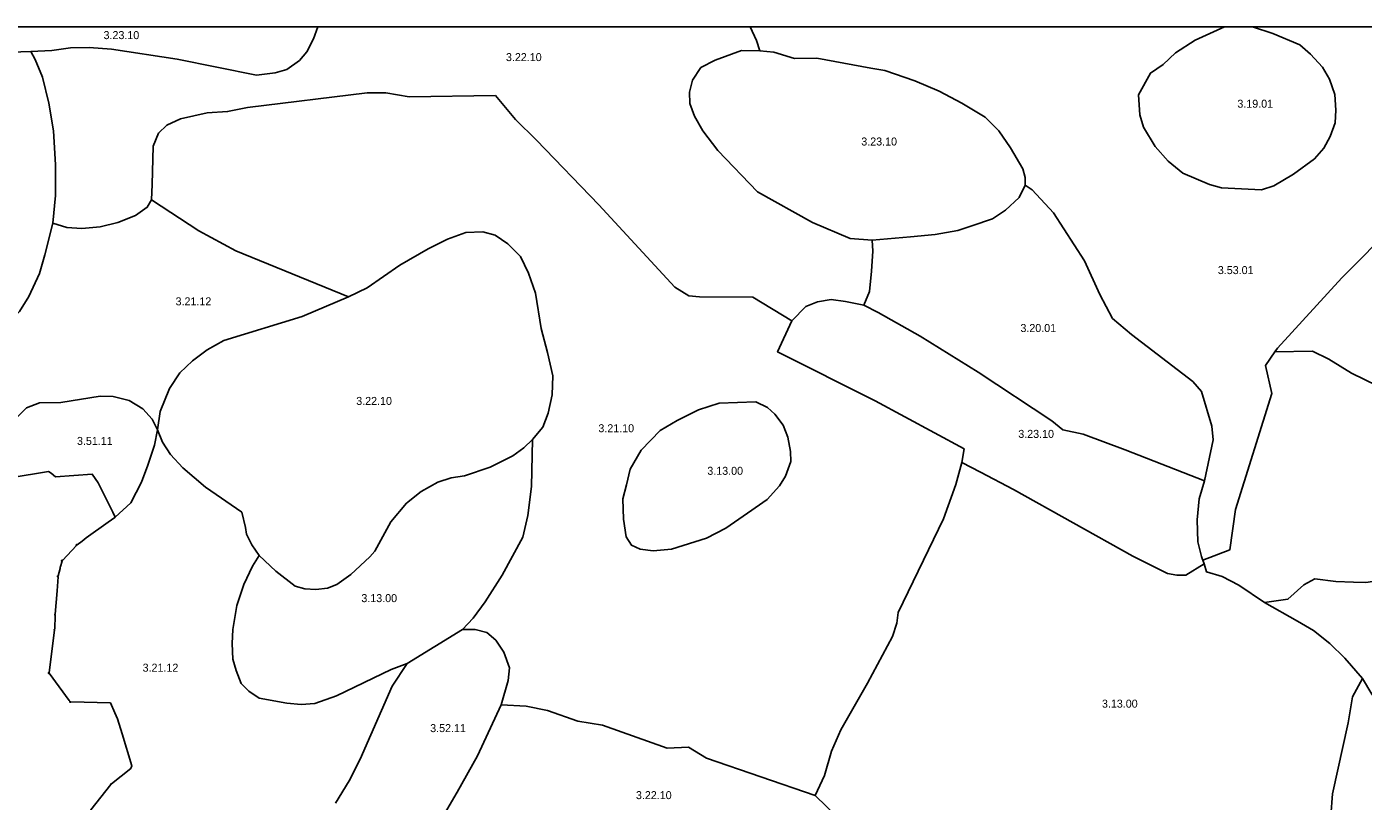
# Model space of a CAD drawing. Extents: x -662500 to -653478, y -1056827 to -1049993.
# Drawn here: x -661381 to -660129, y -1050726 to -1050000 of the extents above; entities that cross this region are included whole.
import ezdxf

# ---------------------------------------------------------------- set-up
doc = ezdxf.new("R2010")
doc.units = 0
doc.layers.add('Vrstva 24', color=7, linetype='Continuous')

msp = doc.modelspace()

# ---------------------------------------------------------------- linework, layer by layer
at = {"layer": 'Vrstva 24'}
for points in [[(-661523.5, -1050000), (-661108.3, -1050000)], [(-661377.4, -1050023.3), (-661357.8, -1050022.2), (-661340.2, -1050019.7), (-661322.6, -1050019.4), (-661301.7, -1050021.1), (-661240.1, -1050030.4), (-661165.8, -1050045.3), (-661148.3, -1050043.1), (-661137.3, -1050040.1), (-661125.7, -1050031.8), (-661118.6, -1050023.6), (-661112.5, -1050011.2), (-661108.3, -1050000)], [(-661108.3, -1050000), (-660703.4, -1050000)], [(-660703.4, -1050000), (-660258.7, -1050000)], [(-660694.1, -1050022.7), (-660697.3, -1050012.8), (-660703.4, -1050000)], [(-660258.7, -1050000), (-660286.3, -1050012.7), (-660304.7, -1050024.5), (-660316.3, -1050035.5), (-660328.1, -1050043.5), (-660339.4, -1050063.9), (-660338.1, -1050082.6), (-660334.8, -1050094.2), (-660323.7, -1050112.1), (-660311.6, -1050126.1), (-660297.8, -1050137.1), (-660272.8, -1050147.9), (-660261.5, -1050150.9), (-660224.1, -1050152.8), (-660212.5, -1050149.2), (-660194, -1050138.2), (-660174.5, -1050123.9), (-660165.7, -1050113.7), (-660159.6, -1050103), (-660155.2, -1050090), (-660154.4, -1050078.2), (-660155.5, -1050063.6), (-660160.5, -1050049), (-660166.8, -1050038), (-660178.3, -1050025.6), (-660188.3, -1050017.1), (-660213.6, -1050006.3), (-660232.6, -1050000)], [(-660258.7, -1050000), (-660232.6, -1050000)], [(-660232.6, -1050000), (-660083.8, -1050000)], [(-660211.6, -1050304.5), (-660209.1, -1050301.1), (-660148.9, -1050235.3), (-660049.3, -1050135), (-660047.7, -1050118.2), (-660049.1, -1050094), (-660056.1, -1050060.4), (-660067.9, -1050029.3), (-660083.8, -1050000)], [(-661463.8, -1050026.3), (-661450.6, -1050027.4), (-661433.8, -1050025.2), (-661377.4, -1050023.3)], [(-661377.4, -1050023.3), (-661373.2, -1050030.7), (-661366.5, -1050047.2), (-661360.4, -1050071.7), (-661356, -1050097.4), (-661354.1, -1050129.3), (-661354.2, -1050158.2), (-661356.7, -1050184.1)], [(-660694.1, -1050022.7), (-660711.4, -1050022.2), (-660735.9, -1050031.3), (-660749.4, -1050038.2), (-660757.4, -1050050), (-660760.1, -1050061.3), (-660759.9, -1050071.8), (-660755.5, -1050083.9), (-660747.5, -1050097.6), (-660733.4, -1050116.1), (-660696.4, -1050154.6), (-660644.9, -1050183.3), (-660609.4, -1050198.4), (-660588.9, -1050200.1)], [(-660445.7, -1050148.6), (-660445.7, -1050141.4), (-660447.8, -1050133.2), (-660459.3, -1050113.6), (-660470.1, -1050097.6), (-660483, -1050084.7), (-660505, -1050071.5), (-660526, -1050060.5), (-660548.8, -1050050.6), (-660577, -1050040.9), (-660590.2, -1050038.7), (-660640.9, -1050029.6), (-660661.6, -1050029.9), (-660681.1, -1050023.8), (-660694.1, -1050022.7)], [(-660664.2, -1050275.5), (-660700.8, -1050253.5), (-660750.6, -1050253.2), (-660760.8, -1050252.1), (-660774, -1050243.9), (-660845.2, -1050167), (-660903.6, -1050106.4), (-660923.3, -1050086.9), (-660942, -1050064.3), (-661022.7, -1050065.7), (-661044.7, -1050061.8), (-661062.3, -1050061.8), (-661174.3, -1050075.6), (-661193, -1050079.5), (-661212, -1050080.6), (-661237.2, -1050086.4), (-661249.8, -1050092.1), (-661257.8, -1050099.6), (-661262.8, -1050111.9), (-661263.6, -1050148), (-661264.2, -1050162.1)], [(-661356.7, -1050184.1), (-661364.2, -1050213.8), (-661369.1, -1050231.4), (-661379.3, -1050252.9), (-661388.1, -1050267), (-661399.4, -1050279.1), (-661411, -1050288.2), (-661419.5, -1050291.5), (-661429.7, -1050291.5), (-661439.6, -1050289.5), (-661453.1, -1050281), (-661463.8, -1050267.8), (-661469.1, -1050256.8), (-661473.6, -1050232.3), (-661477.7, -1050204.7), (-661479.4, -1050161.5), (-661478.8, -1050137), (-661473.6, -1050080.3)], [(-660588.9, -1050200.1), (-660553.1, -1050196.8), (-660529.9, -1050194.8), (-660508.7, -1050191), (-660495.5, -1050186.6), (-660476.2, -1050180), (-660464.1, -1050172), (-660451.2, -1050160.1), (-660445.7, -1050148.6)], [(-660277.5, -1050425.5), (-660269.5, -1050387), (-660270.6, -1050374.3), (-660280.2, -1050341.8), (-660288.5, -1050332.5), (-660346, -1050288.4), (-660363.7, -1050273.3), (-660375.5, -1050251), (-660390, -1050219.3), (-660418.9, -1050174.4), (-660439, -1050152.9), (-660445.7, -1050148.6)], [(-661356.7, -1050184.1), (-661343.6, -1050188.1), (-661329.6, -1050189.2), (-661312.5, -1050187.6), (-661295.7, -1050183.5), (-661279.2, -1050176.9), (-661268.2, -1050169.1), (-661264.2, -1050162.1)], [(-661264.2, -1050162.1), (-661220, -1050191.2), (-661185.3, -1050210), (-661079.8, -1050253.2)], [(-661079.8, -1050253.2), (-661062.2, -1050244.7), (-661031.5, -1050223.5), (-661005.1, -1050208.1), (-660986.9, -1050199), (-660969.8, -1050192.9), (-660953.8, -1050192.1), (-660942.3, -1050195.4), (-660930.4, -1050203.6), (-660918.6, -1050215.2), (-660910.9, -1050230.9), (-660904.3, -1050249.6), (-660899.2, -1050282.7), (-660893.1, -1050305.2), (-660888.2, -1050327), (-660888.7, -1050344.9), (-660892.6, -1050362), (-660897.7, -1050375.2), (-660907.3, -1050386.8)], [(-660596.7, -1050260.9), (-660591.5, -1050248.2), (-660589.6, -1050229.2), (-660588.2, -1050210.2), (-660588.9, -1050200.1)], [(-661079.8, -1050253.2), (-661123, -1050271.4), (-661196.4, -1050294), (-661212.1, -1050302.8), (-661225.9, -1050313), (-661237.7, -1050324.2), (-661247.4, -1050339.1), (-661256.2, -1050360.6), (-661258.5, -1050377.9)], [(-660596.7, -1050260.9), (-660613.8, -1050257.6), (-660627.3, -1050255.7), (-660640.2, -1050257.9), (-660651.2, -1050262.3), (-660664.2, -1050275.5)], [(-660277.5, -1050425.5), (-660352, -1050396.6), (-660391.3, -1050381.8), (-660410.3, -1050377.9), (-660420.7, -1050369.4), (-660489.5, -1050323.6), (-660544, -1050290.1), (-660583.2, -1050267.8), (-660596.7, -1050260.9)], [(-660505, -1050408.5), (-660502.8, -1050395.6), (-660586, -1050350.7), (-660677.5, -1050304.7), (-660664.2, -1050275.5)], [(-660279.1, -1050499.9), (-660253.8, -1050490.3), (-660248.4, -1050452.3), (-660214.5, -1050343.8), (-660220.3, -1050317.6), (-660211.6, -1050304.5)], [(-660211.6, -1050304.5), (-660176.2, -1050303.9), (-660161.1, -1050311.5), (-660139.9, -1050324.5), (-660079.5, -1050353.9), (-660071.9, -1050356.5), (-660062.9, -1050361.1), (-660057, -1050366.9), (-660044.6, -1050380.4)], [(-661258.5, -1050377.9), (-661263.6, -1050367.8), (-661272.4, -1050358.1), (-661285.1, -1050350.1), (-661300.2, -1050346.6), (-661312.3, -1050346.3), (-661349.2, -1050352.1), (-661369.1, -1050352.3), (-661381.5, -1050357), (-661395.8, -1050371.6), (-661404.9, -1050386.2), (-661415.3, -1050423.4), (-661417.3, -1050430.4)], [(-661298.2, -1050459.6), (-661298.2, -1050459.7), (-661283.5, -1050446.3), (-661273.7, -1050426.7), (-661267.6, -1050410.7), (-661261.5, -1050392), (-661258.5, -1050377.9)], [(-661258.5, -1050377.9), (-661253.8, -1050389.2), (-661246.4, -1050400.8), (-661234.8, -1050413.2), (-661213.6, -1050431.6), (-661179.6, -1050455), (-661176.1, -1050469.4), (-661175.2, -1050475.4), (-661170.3, -1050485.6), (-661163.5, -1050495.5)], [(-661163.5, -1050495.5), (-661147.8, -1050510.1), (-661129.7, -1050524.1), (-661120.6, -1050526.6), (-661110.4, -1050527.4), (-661099.4, -1050526.1), (-661090.6, -1050522.8), (-661077.6, -1050513.4), (-661059.7, -1050496.9), (-661054.9, -1050491.4), (-661040, -1050463.9), (-661025.4, -1050446.5), (-661011.7, -1050435.5), (-660996, -1050426.7), (-660983.6, -1050422.8), (-660970.9, -1050420.9), (-660947, -1050412.6), (-660925.8, -1050402.2), (-660915.3, -1050394.7), (-660907.3, -1050386.8)], [(-660972.8, -1050564.9), (-660962.7, -1050554.2), (-660951.6, -1050539), (-660935.7, -1050514), (-660916.3, -1050478.4), (-660911.6, -1050458.1), (-660908.3, -1050430.8), (-660907.3, -1050386.8)], [(-660642.4, -1050720.5), (-660633.7, -1050701.7), (-660627.1, -1050678.9), (-660618.3, -1050658.8), (-660593.3, -1050615), (-660570, -1050571.5), (-660565.9, -1050558.8), (-660564.5, -1050548.8), (-660522, -1050461.1), (-660510.5, -1050429.1), (-660505, -1050408.5)], [(-660277.9, -1050503.2), (-660295.1, -1050513.9), (-660303.4, -1050513.9), (-660312.2, -1050512.3), (-660344.7, -1050496), (-660456.6, -1050433.8), (-660487.4, -1050417.3), (-660505, -1050408.5)], [(-661298.2, -1050459.6), (-661300.5, -1050454.9), (-661311.1, -1050433.8), (-661314.2, -1050427.5), (-661319.8, -1050419.4), (-661354.2, -1050421.7), (-661358.3, -1050418.4), (-661360.9, -1050416.9), (-661396.8, -1050422.6), (-661417.3, -1050430.4)], [(-660277.5, -1050425.5), (-660282.4, -1050442.3), (-660284.4, -1050462.1), (-660283.8, -1050482.8), (-660280.4, -1050496.3), (-660279.7, -1050498.3), (-660279.1, -1050499.9)], [(-661298.2, -1050459.6), (-661298.5, -1050459.8), (-661304.8, -1050464.3), (-661325.6, -1050478.8), (-661329.2, -1050482), (-661334, -1050485.5), (-661334, -1050485.4), (-661334, -1050485.4), (-661334, -1050485.4), (-661334, -1050485.4), (-661334.1, -1050485.4), (-661334.1, -1050485.3), (-661334.1, -1050485.3), (-661334.2, -1050485.3), (-661334.2, -1050485.3), (-661334.2, -1050485.3), (-661334.2, -1050485.3), (-661334.3, -1050485.3), (-661334.3, -1050485.3), (-661334.3, -1050485.3), (-661334.4, -1050485.3), (-661334.4, -1050485.3), (-661334.4, -1050485.3), (-661334.5, -1050485.3), (-661334.5, -1050485.3), (-661334.5, -1050485.3), (-661334.5, -1050485.3), (-661334.6, -1050485.3), (-661334.6, -1050485.3), (-661334.6, -1050485.3), (-661334.7, -1050485.4), (-661334.7, -1050485.4), (-661334.7, -1050485.4), (-661334.7, -1050485.4), (-661334.8, -1050485.5), (-661334.8, -1050485.5), (-661334.8, -1050485.5), (-661334.8, -1050485.6), (-661334.8, -1050485.6), (-661334.8, -1050485.6), (-661334.8, -1050485.6), (-661334.8, -1050485.7), (-661334.9, -1050485.7), (-661334.9, -1050485.7), (-661334.9, -1050485.8), (-661334.9, -1050485.8), (-661334.9, -1050485.8), (-661334.8, -1050485.9), (-661334.8, -1050485.9), (-661334.8, -1050485.9), (-661334.8, -1050485.9), (-661334.8, -1050486), (-661334.8, -1050486), (-661334.8, -1050486), (-661334.8, -1050486.1), (-661334.7, -1050486.1), (-661334.7, -1050486.1), (-661334.7, -1050486.1), (-661347.7, -1050500.1), (-661347.7, -1050500.1), (-661347.7, -1050500.1), (-661347.8, -1050500.1), (-661347.8, -1050500), (-661347.8, -1050500), (-661347.8, -1050500)], [(-661347.8, -1050500), (-661347.9, -1050500), (-661347.9, -1050500), (-661347.9, -1050500), (-661347.9, -1050500), (-661348, -1050500), (-661348, -1050500), (-661348, -1050500), (-661348.1, -1050500), (-661348.1, -1050500), (-661348.1, -1050500), (-661348.2, -1050500), (-661348.2, -1050500), (-661348.2, -1050500), (-661348.2, -1050500), (-661348.3, -1050500.1), (-661348.3, -1050500.1), (-661348.3, -1050500.1), (-661348.4, -1050500.1), (-661348.4, -1050500.1), (-661348.4, -1050500.2), (-661348.4, -1050500.2), (-661348.5, -1050500.2), (-661348.5, -1050500.3), (-661348.5, -1050500.3), (-661348.5, -1050500.3), (-661348.5, -1050500.4), (-661348.5, -1050500.4), (-661348.5, -1050500.4), (-661348.5, -1050500.4), (-661348.5, -1050500.5), (-661348.5, -1050500.5), (-661348.5, -1050500.5), (-661348.5, -1050500.6), (-661348.5, -1050500.6), (-661348.5, -1050500.6), (-661348.5, -1050500.6), (-661348.5, -1050500.7), (-661348.5, -1050500.7), (-661348.4, -1050500.7), (-661348.4, -1050500.8), (-661348.4, -1050500.8), (-661348.4, -1050500.8), (-661348.3, -1050500.9), (-661348.3, -1050500.9), (-661348.3, -1050500.9), (-661348.2, -1050500.9), (-661348.2, -1050500.9), (-661348.2, -1050500.9), (-661348.2, -1050500.9), (-661348.1, -1050500.9), (-661349.4, -1050505.8), (-661349.8, -1050506.3), (-661349.9, -1050507.8), (-661351.7, -1050514.6), (-661351.7, -1050514.6), (-661351.7, -1050514.6), (-661351.7, -1050514.6), (-661351.8, -1050514.6), (-661351.8, -1050514.6), (-661351.8, -1050514.6), (-661351.9, -1050514.6), (-661351.9, -1050514.6), (-661351.9, -1050514.6), (-661352, -1050514.6)], [(-661024.6, -1050596.6), (-661039.6, -1050602.4), (-661090.8, -1050627.1), (-661111.2, -1050634.3), (-661124.1, -1050635.1), (-661137.4, -1050634), (-661163.5, -1050629.3), (-661173.2, -1050622.7), (-661180.3, -1050615.6), (-661185, -1050603.4), (-661188, -1050592.7), (-661188.6, -1050578.1), (-661188, -1050564.9), (-661184.2, -1050542.3), (-661177.6, -1050522.8), (-661169.6, -1050505.4), (-661163.5, -1050495.5)], [(-660277.9, -1050503.2), (-660279.1, -1050499.9)], [(-661352, -1050514.6), (-661352, -1050514.6), (-661352, -1050514.6), (-661352, -1050514.6), (-661352.1, -1050514.7), (-661352.1, -1050514.7), (-661352.1, -1050514.7), (-661352.2, -1050514.7), (-661352.2, -1050514.8), (-661352.2, -1050514.8), (-661352.2, -1050514.8), (-661352.2, -1050514.9), (-661352.2, -1050514.9), (-661352.2, -1050514.9), (-661352.3, -1050514.9), (-661352.3, -1050515), (-661352.3, -1050515), (-661352.3, -1050515), (-661352.3, -1050515.1), (-661352.3, -1050515.1), (-661352.3, -1050515.1), (-661352.3, -1050515.2), (-661352.3, -1050515.2), (-661352.2, -1050515.2), (-661352.2, -1050515.2), (-661352.2, -1050515.3), (-661352.2, -1050515.3), (-661352.2, -1050515.3), (-661352.2, -1050515.4), (-661352.2, -1050515.4), (-661352.1, -1050515.4), (-661352.1, -1050515.4), (-661352.1, -1050515.5), (-661352, -1050515.5), (-661352, -1050515.5), (-661352, -1050515.5), (-661352, -1050515.5), (-661351.9, -1050515.6), (-661351.9, -1050515.6), (-661351.8, -1050515.6), (-661351.8, -1050515.6), (-661351.8, -1050515.6), (-661352.8, -1050528.7), (-661354.4, -1050550.4), (-661354.4, -1050550.4), (-661354.4, -1050550.4), (-661354.5, -1050550.4), (-661354.5, -1050550.4), (-661354.5, -1050550.4), (-661354.5, -1050550.4), (-661354.6, -1050550.4), (-661354.6, -1050550.4), (-661354.6, -1050550.4), (-661354.7, -1050550.4), (-661354.7, -1050550.4), (-661354.7, -1050550.5), (-661354.7, -1050550.5), (-661354.8, -1050550.5), (-661354.8, -1050550.6), (-661354.8, -1050550.6), (-661354.8, -1050550.6), (-661354.8, -1050550.6), (-661354.9, -1050550.7), (-661354.9, -1050550.7), (-661354.9, -1050550.7)], [(-660221.4, -1050539.5), (-660245.4, -1050523.3), (-660260.8, -1050515.3), (-660275.7, -1050510.8), (-660277.9, -1050503.2)], [(-659949.4, -1050675.3), (-659951.1, -1050674.4), (-659962.6, -1050665.3), (-659970.8, -1050636.2), (-659978.9, -1050606.3), (-659978.4, -1050603.2), (-659962.9, -1050562.2), (-659964.8, -1050560.2), (-659964.1, -1050557.4), (-659986.4, -1050535.2), (-659984.2, -1050529.3), (-660000, -1050522.6), (-660004.8, -1050520.5), (-660009.3, -1050518.3), (-660015, -1050516.2), (-660035.6, -1050507.4), (-660126.2, -1050520.7), (-660138, -1050520.4), (-660154.5, -1050520), (-660174.1, -1050517.5), (-660184.3, -1050523), (-660199.4, -1050536.5), (-660221.4, -1050539.5)], [(-660221.4, -1050539.5), (-660190.3, -1050556.9), (-660175.3, -1050565.7), (-660160.2, -1050578.1), (-660145.9, -1050591.8), (-660129.5, -1050610.8)], [(-661354.9, -1050550.7), (-661354.9, -1050550.8), (-661354.9, -1050550.8), (-661354.9, -1050550.8), (-661354.9, -1050550.9), (-661354.9, -1050550.9), (-661354.9, -1050550.9), (-661354.9, -1050550.9), (-661354.9, -1050551), (-661354.9, -1050551), (-661354.8, -1050551), (-661354.8, -1050551.1), (-661354.8, -1050551.1), (-661354.8, -1050551.1), (-661354.8, -1050551.1), (-661354.8, -1050551.2), (-661354.8, -1050551.2), (-661354.7, -1050551.2), (-661354.7, -1050551.2), (-661354.7, -1050551.3), (-661354.6, -1050551.3), (-661354.6, -1050551.3), (-661354.6, -1050551.3), (-661354.5, -1050551.3), (-661354.5, -1050551.3), (-661354.5, -1050551.4), (-661354.4, -1050551.4), (-661354.4, -1050551.4), (-661355, -1050564.6), (-661355, -1050564.6), (-661355, -1050564.6), (-661355.1, -1050564.6), (-661355.1, -1050564.6), (-661355.1, -1050564.6), (-661355.2, -1050564.6), (-661355.2, -1050564.6), (-661355.2, -1050564.6), (-661355.2, -1050564.7), (-661355.3, -1050564.7), (-661355.3, -1050564.7), (-661355.3, -1050564.7), (-661355.4, -1050564.8), (-661355.4, -1050564.8), (-661355.4, -1050564.8), (-661355.4, -1050564.8), (-661355.4, -1050564.9), (-661355.5, -1050564.9), (-661355.5, -1050564.9), (-661355.5, -1050565), (-661355.5, -1050565), (-661355.5, -1050565), (-661355.5, -1050565.1), (-661355.5, -1050565.1), (-661355.5, -1050565.1), (-661355.5, -1050565.1), (-661355.5, -1050565.2), (-661355.5, -1050565.2), (-661355.5, -1050565.2), (-661355.4, -1050565.3), (-661355.4, -1050565.3), (-661355.4, -1050565.3), (-661355.4, -1050565.3), (-661355.4, -1050565.4), (-661355.4, -1050565.4), (-661355.3, -1050565.4)], [(-660972.8, -1050564.9), (-661024.6, -1050596.6)], [(-660972.8, -1050564.9), (-660961.1, -1050564.9), (-660950.1, -1050567.6), (-660941.6, -1050574.8), (-660934.2, -1050586.1), (-660928.7, -1050600.7), (-660930, -1050612.5), (-660936.6, -1050635.4)], [(-661355.3, -1050565.4), (-661355.3, -1050565.5), (-661355.3, -1050565.5), (-661355.2, -1050565.5), (-661355.2, -1050565.5), (-661355.2, -1050565.5), (-661355.2, -1050565.6), (-661355.1, -1050565.6), (-661355.1, -1050565.6), (-661355.1, -1050565.6), (-661360.3, -1050605), (-661360.4, -1050605), (-661360.4, -1050605), (-661360.4, -1050605), (-661360.5, -1050605), (-661360.5, -1050605.1), (-661360.5, -1050605.1), (-661360.5, -1050605.1), (-661360.6, -1050605.1), (-661360.6, -1050605.1), (-661360.6, -1050605.1), (-661360.7, -1050605.1), (-661360.7, -1050605.1), (-661360.7, -1050605.2), (-661360.7, -1050605.2), (-661360.8, -1050605.2), (-661360.8, -1050605.2), (-661360.8, -1050605.3), (-661360.8, -1050605.3), (-661360.8, -1050605.3), (-661360.9, -1050605.4), (-661360.9, -1050605.4), (-661360.9, -1050605.4), (-661360.9, -1050605.4), (-661360.9, -1050605.5), (-661360.9, -1050605.5), (-661360.9, -1050605.5), (-661360.9, -1050605.6), (-661360.9, -1050605.6), (-661360.9, -1050605.6), (-661360.9, -1050605.7), (-661360.9, -1050605.7), (-661360.8, -1050605.7), (-661360.8, -1050605.8), (-661360.8, -1050605.8), (-661360.8, -1050605.8), (-661360.8, -1050605.8), (-661360.8, -1050605.9), (-661360.8, -1050605.9), (-661360.7, -1050605.9), (-661360.7, -1050605.9), (-661360.7, -1050606), (-661360.6, -1050606), (-661360.6, -1050606), (-661360.6, -1050606), (-661360.5, -1050606), (-661360.5, -1050606), (-661360.5, -1050606), (-661360.5, -1050606), (-661360.4, -1050606), (-661360.4, -1050606), (-661360.4, -1050606), (-661360.3, -1050606), (-661360.3, -1050606), (-661360.3, -1050606)], [(-661024.6, -1050596.6), (-661038.6, -1050618), (-661068.7, -1050686.3), (-661079, -1050706.7), (-661091.9, -1050727.7)], [(-661360.3, -1050606), (-661360.2, -1050606), (-661360.2, -1050606), (-661360.2, -1050606), (-661360.2, -1050606), (-661360.1, -1050606), (-661360.1, -1050605.9), (-661341.3, -1050631.3), (-661340.7, -1050632.1), (-661340.7, -1050632.1), (-661340.8, -1050632.1), (-661340.8, -1050632.1), (-661340.8, -1050632.2), (-661340.8, -1050632.2), (-661340.8, -1050632.2), (-661340.9, -1050632.3), (-661340.9, -1050632.3), (-661340.9, -1050632.3), (-661340.9, -1050632.4), (-661340.9, -1050632.4), (-661340.9, -1050632.4), (-661340.9, -1050632.4), (-661340.9, -1050632.5), (-661340.9, -1050632.5), (-661340.9, -1050632.5), (-661340.9, -1050632.6), (-661340.9, -1050632.6), (-661340.9, -1050632.6), (-661340.9, -1050632.6), (-661340.9, -1050632.7), (-661340.8, -1050632.7), (-661340.8, -1050632.7), (-661340.8, -1050632.8), (-661340.8, -1050632.8), (-661340.8, -1050632.8), (-661340.7, -1050632.9), (-661340.7, -1050632.9), (-661340.7, -1050632.9), (-661340.7, -1050632.9), (-661340.6, -1050632.9), (-661340.6, -1050632.9), (-661340.6, -1050632.9), (-661340.5, -1050633), (-661340.5, -1050633), (-661340.5, -1050633), (-661340.4, -1050633), (-661340.4, -1050633), (-661340.4, -1050633), (-661340.3, -1050633), (-661340.3, -1050633), (-661340.3, -1050633), (-661340.3, -1050632.9), (-661340.2, -1050632.9), (-661340.2, -1050632.9), (-661340.2, -1050632.9), (-661340.1, -1050632.9), (-661340.1, -1050632.9), (-661340.1, -1050632.9), (-661340.1, -1050632.8), (-661340, -1050632.8), (-661340, -1050632.8), (-661340, -1050632.7), (-661340, -1050632.7), (-661340, -1050632.7), (-661339.9, -1050632.6)], [(-660129.5, -1050610.8), (-660138.7, -1050627.9), (-660142.8, -1050652.4), (-660157.6, -1050718.8), (-660159, -1050739.4)], [(-660129.5, -1050610.8), (-660120.8, -1050625.4), (-660109, -1050640.6), (-660084.5, -1050681.1), (-660065.5, -1050706.7), (-660062.7, -1050711.6)], [(-661339.9, -1050632.6), (-661339.9, -1050632.6), (-661339.9, -1050632.6), (-661339.9, -1050632.6), (-661339.9, -1050632.5), (-661339.9, -1050632.5), (-661302.7, -1050633.5), (-661298.7, -1050642.9), (-661296.2, -1050648.6), (-661291.9, -1050662.7), (-661282.6, -1050692.7), (-661283.5, -1050695.1), (-661301.7, -1050709.5), (-661301.7, -1050709.5), (-661301.7, -1050709.5), (-661301.7, -1050709.5), (-661301.8, -1050709.4), (-661301.8, -1050709.4), (-661301.8, -1050709.4), (-661301.8, -1050709.4), (-661301.9, -1050709.4), (-661301.9, -1050709.4), (-661301.9, -1050709.4), (-661302, -1050709.4), (-661302, -1050709.4), (-661302, -1050709.3), (-661302, -1050709.3), (-661302.1, -1050709.3), (-661302.1, -1050709.3), (-661302.1, -1050709.4), (-661302.2, -1050709.4), (-661302.2, -1050709.4), (-661302.2, -1050709.4), (-661302.2, -1050709.4), (-661302.3, -1050709.4), (-661302.3, -1050709.4), (-661302.3, -1050709.4), (-661302.4, -1050709.5), (-661302.4, -1050709.5), (-661302.4, -1050709.5), (-661302.4, -1050709.5), (-661302.5, -1050709.6), (-661302.5, -1050709.6), (-661302.5, -1050709.6), (-661302.5, -1050709.7), (-661302.5, -1050709.7), (-661302.5, -1050709.7), (-661302.5, -1050709.8), (-661302.5, -1050709.8), (-661302.5, -1050709.8), (-661302.5, -1050709.8), (-661302.5, -1050709.9), (-661302.5, -1050709.9), (-661302.5, -1050709.9), (-661302.5, -1050710), (-661302.5, -1050710), (-661302.5, -1050710), (-661302.5, -1050710.1), (-661302.5, -1050710.1), (-661302.5, -1050710.1), (-661302.4, -1050710.1), (-661302.4, -1050710.2), (-661302.4, -1050710.2), (-661302.4, -1050710.2), (-661302.3, -1050710.2)], [(-660992, -1050741.4), (-660977.7, -1050717.4), (-660958.7, -1050683.3), (-660936.6, -1050635.4)], [(-660642.4, -1050720.5), (-660744.2, -1050685.5), (-660760.9, -1050675.1), (-660781.1, -1050676.1), (-660841.5, -1050654.6), (-660864.6, -1050650.8), (-660893.3, -1050640.6), (-660913.1, -1050636.8), (-660936.6, -1050635.4)], [(-661302.3, -1050710.2), (-661321, -1050733.8), (-661321.3, -1050734.2), (-661321.2, -1050734.7), (-661318.8, -1050741.1), (-661319, -1050741.7)], [(-660497.9, -1050811.3), (-660522.9, -1050802), (-660549.1, -1050788.2), (-660596.7, -1050756.8), (-660621.5, -1050740.6), (-660642.4, -1050720.5)]]:
    msp.add_lwpolyline(points, dxfattribs=at)
msp.add_lwpolyline([(-660744.2, -1050479.3), (-660726, -1050469.9), (-660705.6, -1050455.9), (-660687.2, -1050442.9), (-660675.9, -1050430.3), (-660670.1, -1050421.2), (-660665.1, -1050407.4), (-660665.4, -1050398), (-660667.9, -1050384.6), (-660672.3, -1050373.5), (-660680, -1050363.1), (-660686.9, -1050356.7), (-660697.9, -1050351.5), (-660732.3, -1050352.6), (-660751.6, -1050358.9), (-660771.7, -1050369.1), (-660787.5, -1050378.5), (-660805.4, -1050396.9), (-660815.6, -1050414.6), (-660819.2, -1050429.4), (-660822.5, -1050442.4), (-660821.8, -1050461.4), (-660819.6, -1050477.9), (-660814.4, -1050485.9), (-660806.4, -1050489.7), (-660794, -1050491.1), (-660776.9, -1050489.5)], close=True, dxfattribs=at)

# ---------------------------------------------------------------- texts
for s, p in [('3.23.10', (-661309.2, -1050011.6)), ('3.22.10', (-660932.1, -1050032.2)), ('3.19.01', (-660246.7, -1050075.9)), ('3.23.10', (-660599.1, -1050111.3)), ('3.53.01', (-660265, -1050231.8)), ('3.21.12', (-661241.7, -1050261.1)), ('3.20.01', (-660450, -1050286.1)), ('3.22.10', (-661072.4, -1050354.4)), ('3.21.10', (-660845.5, -1050380)), ('3.51.11', (-661334.1, -1050391.9)), ('3.23.10', (-660452, -1050385.3)), ('3.13.00', (-660743.4, -1050419.9)), ('3.13.00', (-661067.6, -1050539.2)), ('3.21.12', (-661272.6, -1050604.4)), ('3.13.00', (-660373.6, -1050638.1)), ('3.52.11', (-661003.1, -1050661)), ('3.22.10', (-660810.3, -1050723.8))]:
    msp.add_text(s, height=7.5, dxfattribs=at).set_placement(p)

doc.saveas('drawing.dxf')
